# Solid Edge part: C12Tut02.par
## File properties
Author: ASHUTOSH
Template: iso metric part.par
Last saved by: ASHUTOSH
Revision: 2
Application: Solid Edge
Accuracy: 0.990
Username: ASHUTOSH
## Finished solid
Body 1: solid body, 20 faces, 54 edges, 36 vertices.
  Faces by surface: plane 13, cylinder 7
  Edges by curve: line 40, circle 14
Bounding box of the edges (mm): 175.000 x 50.000 x 89.138, from (-48, -25, 0) to (127, 25, 89.1384).
Cylindrical faces by radius (mm): R5 x2, R6 x1, R9.7733 x1, R15 x2, R27 x1
Planar faces by outward normal: +y 3, +z 1, -y 3, -z 1, oblique 5
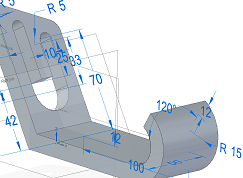
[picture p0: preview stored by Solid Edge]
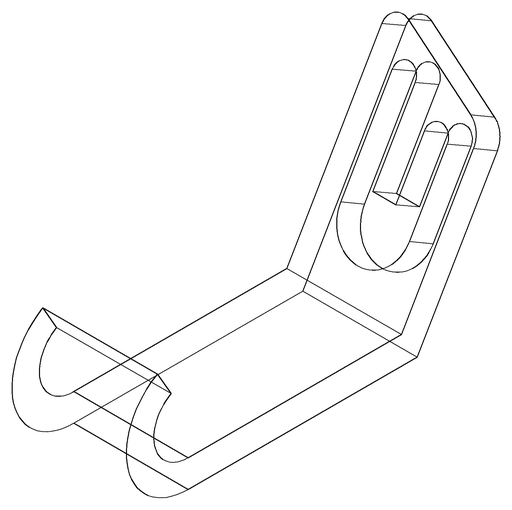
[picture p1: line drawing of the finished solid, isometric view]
